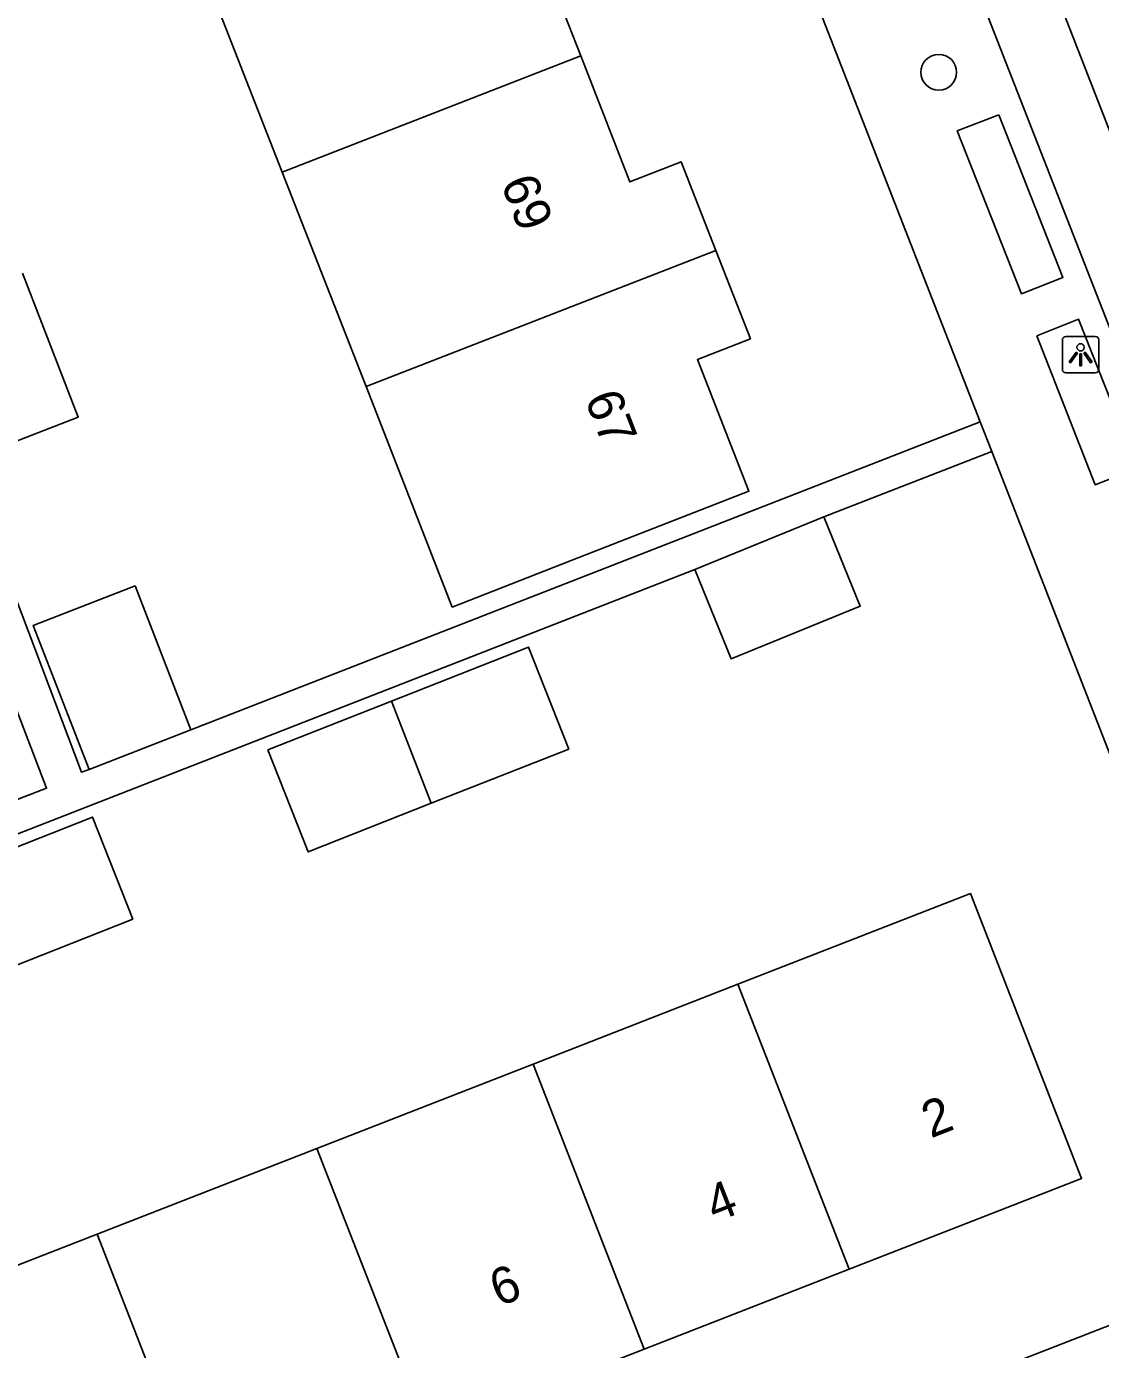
# Model space of a CAD drawing. Extents: x 159689 to 160786, y 387323 to 388339.
# Drawn here: x 160147.49 to 160176.88, y 387810.77 to 387846.99 of the extents above; entities that cross this region are included whole.
import ezdxf

# ---------------------------------------------------------------- set-up
doc = ezdxf.new("R2010")
doc.units = 0
for name, color, linetype in [('IMGEO_Boom', 7, 'Continuous'), ('IMGEO_Lichtpunt', 7, 'Continuous'), ('IMGEO_Pand', 7, 'Continuous'), ('IMGEO_Pand_nummerreeks', 7, 'Continuous'), ('IMGEO_Rijbaan_lokaal_gesloten', 7, 'Continuous'), ('IMGEO_Voetpad_open', 7, 'Continuous')]:
    doc.layers.add(name, color=color, linetype=linetype)

msp = doc.modelspace()

# ---------------------------------------------------------------- linework, layer by layer
at = {"layer": 'IMGEO_Boom'}
msp.add_circle((160172.454, 387845.734), 0.489, dxfattribs=at)
at = {"layer": 'IMGEO_Lichtpunt'}
for p, q in [((160175.837, 387838.408), (160175.837, 387837.601)), ((160175.837, 387838.408), (160175.837, 387837.601)), ((160176.739, 387838.503), (160175.931, 387838.503)), ((160176.739, 387838.503), (160175.931, 387838.503)), ((160176.833, 387837.601), (160176.833, 387838.408)), ((160176.833, 387837.601), (160176.833, 387838.408)), ((160175.931, 387837.507), (160176.739, 387837.507)), ((160175.931, 387837.507), (160176.739, 387837.507))]:
    msp.add_line(p, q, dxfattribs=at)
for points in [[(160176.211, 387838.072), (160176.25, 387838.044), (160176.062, 387837.782), (160176.024, 387837.809), (160176.211, 387838.072)], [(160176.313, 387838.024), (160176.36, 387838.024), (160176.36, 387837.702), (160176.313, 387837.702), (160176.313, 387838.024)], [(160176.423, 387838.044), (160176.461, 387838.071), (160176.648, 387837.809), (160176.609, 387837.781), (160176.423, 387838.044)]]:
    msp.add_lwpolyline(points, dxfattribs=at)
msp.add_circle((160176.336, 387838.206), 0.0994, dxfattribs=at)
for centre, start, end in [((160175.931, 387838.408), 90, 180), ((160175.931, 387838.408), 90, 180), ((160176.739, 387838.408), 0, 90), ((160176.739, 387838.408), 0, 90), ((160175.931, 387837.601), 180, 270), ((160175.931, 387837.601), 180, 270), ((160176.739, 387837.601), 270, 0), ((160176.739, 387837.601), 270, 360)]:
    msp.add_arc(centre, 0.0946, start, end, dxfattribs=at)
at = {"layer": 'IMGEO_Pand'}
for points in [[(160161.797, 387852.57), (160162.73, 387850.184), (160161.308, 387849.628), (160162.656, 387846.181)], [(160154.486, 387843.001), (160152.205, 387848.836)], [(160162.656, 387846.181), (160154.486, 387843.001)], [(160162.656, 387846.181), (160164.004, 387842.733), (160165.408, 387843.282), (160166.355, 387840.86)], [(160156.781, 387837.133), (160154.486, 387843.001)], [(160166.355, 387840.86), (160167.301, 387838.44), (160165.851, 387837.872), (160167.259, 387834.27), (160162.603, 387832.45), (160159.141, 387831.096), (160156.781, 387837.133)], [(160156.781, 387837.133), (160166.355, 387840.86)], [(160147.376, 387840.233), (160148.901, 387836.292), (160146.026, 387835.18), (160144.503, 387839.115)], [(160144.956, 387825.523), (160145.145, 387825.029), (160148.036, 387826.138), (160145.159, 387833.643)], [(160169.306, 387833.564), (160170.304, 387831.121), (160166.776, 387829.679), (160165.778, 387832.123)], [(160169.306, 387833.564), (160165.778, 387832.123)], [(160149.203, 387826.653), (160147.671, 387830.593), (160150.458, 387831.677), (160151.99, 387827.737)], [(160157.475, 387828.522), (160161.226, 387830.002), (160162.328, 387827.21), (160158.566, 387825.725)], [(160158.566, 387825.725), (160155.198, 387824.395), (160154.096, 387827.188), (160157.475, 387828.522)], [(160158.566, 387825.725), (160157.475, 387828.522)], [(160149.203, 387826.653), (160151.99, 387827.737)], [(160145.542, 387823.867), (160149.293, 387825.347), (160150.395, 387822.555), (160146.633, 387821.07)], [(160166.955, 387820.772), (160173.322, 387823.255), (160176.365, 387815.454), (160169.998, 387812.971)], [(160161.351, 387818.586), (160166.955, 387820.772)], [(160166.955, 387820.772), (160169.998, 387812.971)], [(160155.436, 387816.278), (160161.351, 387818.586)], [(160164.394, 387810.785), (160161.351, 387818.586)], [(160149.418, 387813.931), (160155.436, 387816.278)], [(160155.436, 387816.278), (160158.48, 387808.478)], [(160143.73, 387811.712), (160149.418, 387813.931)], [(160152.461, 387806.13), (160149.418, 387813.931)], [(160169.998, 387812.971), (160164.394, 387810.785)], [(160164.394, 387810.785), (160158.48, 387808.478)]]:
    msp.add_lwpolyline(points, dxfattribs=at)
at = {"layer": 'IMGEO_Rijbaan_lokaal_gesloten'}
msp.add_lwpolyline([(160153.484, 387904.909), (160170.802, 387860.362), (160186.371, 387820.436)], dxfattribs=at)
at = {"layer": 'IMGEO_Voetpad_open'}
for points in [[(160151.872, 387903.499), (160169.005, 387859.521), (160184.374, 387820.228)], [(160173.59, 387836.163), (160150.403, 387895.606)], [(160141.351, 387846.812), (160148.995, 387826.575), (160149.203, 387826.653)], [(160174.1, 387844.571), (160172.962, 387844.136), (160174.719, 387839.671), (160175.853, 387840.12), (160174.1, 387844.571)], [(160175.134, 387838.523), (160176.737, 387834.443), (160177.893, 387834.899), (160176.279, 387838.981), (160175.134, 387838.523)], [(160151.99, 387827.737), (160173.59, 387836.163)], [(160173.59, 387836.163), (160173.904, 387835.358)], [(160173.904, 387835.358), (160169.306, 387833.564)], [(160181.811, 387815.087), (160173.904, 387835.358)], [(160165.778, 387832.123), (160125.587, 387816.432)], [(160180.841, 387812.88), (160130.55, 387793.293)]]:
    msp.add_lwpolyline(points, dxfattribs=at)

# ---------------------------------------------------------------- texts
at = {"layer": 'IMGEO_Pand_nummerreeks'}
for s, rotation, p in [('69', 291.268, (160160.459, 387842.697)), ('67', 291.268, (160162.755, 387836.799)), ('2', 21.309, (160172.235, 387816.548)), ('4', 21.309, (160166.326, 387814.243)), ('6', 21.309, (160160.415, 387811.938))]:
    msp.add_text(s, height=1, rotation=rotation, dxfattribs=at).set_placement(p)

doc.saveas('drawing.dxf')
